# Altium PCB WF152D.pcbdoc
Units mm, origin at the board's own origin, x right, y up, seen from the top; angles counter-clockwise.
Board outline 18.64 x 18.64 mm, 2 copper layers (Top Layer, Bottom Layer); 1 components, 0 nets, 4 pads, 0 vias.
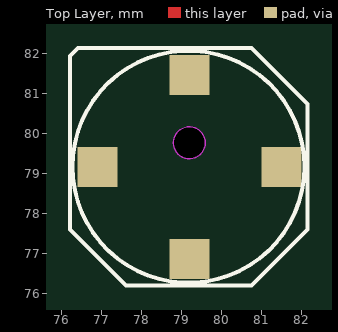
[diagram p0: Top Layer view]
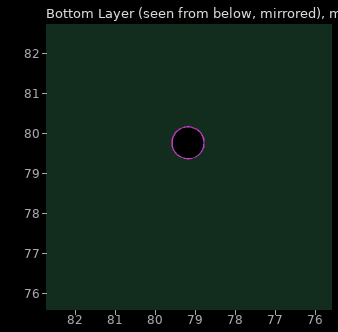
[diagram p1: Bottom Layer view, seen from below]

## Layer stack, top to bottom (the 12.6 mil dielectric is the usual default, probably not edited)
Top Layer: signal copper (thickness not stored)
Dielectric: dielectric 0.32, FR-4, Dk 4.8
Bottom Layer: signal copper (thickness not stored)

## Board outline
88.49,69.85 69.85,69.85 69.85,88.49 88.49,88.49

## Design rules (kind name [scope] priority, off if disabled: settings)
BoardOutlineClearance safeClearance [All] p0: genericclearance=0.254 ignorepadtopadclearanceinfootprint=FALSE except(0: Arc-SplitContinuation Track-SplitContinuation SMDPad-SplitContinuation THPad-SplitContinuation Via-SplitContinuation Fill-SplitContinuation Poly-SplitContinuation Region-SplitContinuation Text-SplitContinuation; 0.152: Track-CutoutEdge SMDPad-CutoutEdge THPad-CutoutEdge Via-CutoutEdge Fill-CutoutEdge Region-CutoutEdge; 0.3: Track-OutlineEdge SMDPad-OutlineEdge THPad-OutlineEdge Via-OutlineEdge Fill-OutlineEdge Region-OutlineEdge Poly-OutlineEdge Text-OutlineEdge)
Clearance safeClearance [All] p1: gap=0.178 ignorepadtopadclearanceinfootprint=FALSE except(0.152: Track-Track Track-SMDPad SMDPad-SMDPad Track-THPad SMDPad-THPad THPad-THPad Track-Via SMDPad-Via THPad-Via Via-Via Track-Fill SMDPad-Fill THPad-Fill Via-Fill Fill-Fill Track-Region SMDPad-Region THPad-Region Via-Region Fill-Region Region-Region Track-Poly SMDPad-Poly THPad-Poly Via-Poly Fill-Poly Region-Poly Poly-Poly Track-Text SMDPad-Text THPad-Text Via-Text Fill-Text Region-Text Poly-Text Text-Text; 0.175: Track-Hole SMDPad-Hole THPad-Hole Via-Hole Fill-Hole Region-Hole Poly-Hole Text-Hole Sheet-Hole; 0.3: Track-Sheet SMDPad-Sheet THPad-Sheet Via-Sheet Fill-Sheet Region-Sheet Poly-Sheet Text-Sheet)
DiffPairsRouting differentialPair [All] p1: maxuncoupledlength=10 minlimit=6 maxlimit=6 mostfreqgap=6 toplayer_minwidth=5 toplayer_prefwidth=10 toplayer_maxwidth=100 bottomlayer_minwidth=5 bottomlayer_prefwidth=10 bottomlayer_maxwidth=100
PasteMaskExpansion pasteMaskExpansion [All] p1: expansion=0
PlaneConnect innerPlane [All] p1: planeconnectstyle=Relief reliefexpansion=0.508 reliefentries=4 reliefconductorwidth=0.254 reliefairgap=0.254
PolygonConnect copperRegion [All] p1: connectstyle=Relief reliefentries=4 reliefconductorwidth=10 polygonreliefangle="90 Angle" airgapwidth=10
RoutingVias viaSize [All] p1: viastyle="Through Hole" holewidth=12.0078 minholewidth=11.811 maxholewidth=236.2204 width=24.0158 minwidth=19.685 maxwidth=393.7008
SolderMaskExpansion solderMaskExpansion [All] p1: useseparateexpansions=TRUE expansion=2 expansionbottom=2
Width trackWidth [All] p1: maxlimit=100 minlimit=5 preferedwidth=10

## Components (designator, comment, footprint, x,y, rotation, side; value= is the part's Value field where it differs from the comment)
? "152D" 152D 79.098,79.109 r0 top

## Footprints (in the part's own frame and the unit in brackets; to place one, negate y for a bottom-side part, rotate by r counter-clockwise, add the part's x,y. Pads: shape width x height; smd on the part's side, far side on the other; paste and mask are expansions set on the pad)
152D [mm]
  rect 1x1 smd: 1(0.088,2.358) 2(-2.212,0.058) 3(0.088,-2.242) 4(2.388,0.058)
  Board Outline Layer circle w0.025: c0.088,0.658 r0.4
  Board Outline Layer region: 0.488,0.658 0.448,0.484 0.337,0.345 0.177,0.268 -0.001,0.268 -0.161,0.345 -0.272,0.484 -0.312,0.658 -0.312,0.658 -0.272,0.831 -0.161,0.97 -0.001,1.048 0.177,1.048 0.337,0.97 0.448,0.831 0.488,0.658
  Multi-Layer board cut-out: 0.488,0.658 0.448,0.484 0.337,0.345 0.177,0.268 -0.001,0.268 -0.161,0.345 -0.272,0.484 -0.312,0.658 -0.312,0.658 -0.272,0.831 -0.161,0.97 -0.001,1.048 0.177,1.048 0.337,0.97 0.448,0.831 0.488,0.658
  silkscreen extent -2.9,-2.91 3.04,3.03

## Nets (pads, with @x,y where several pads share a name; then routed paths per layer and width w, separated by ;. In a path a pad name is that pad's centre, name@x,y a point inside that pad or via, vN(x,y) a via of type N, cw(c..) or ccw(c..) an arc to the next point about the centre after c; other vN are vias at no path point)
pads on no net: ?.1 ?.2 ?.3 ?.4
